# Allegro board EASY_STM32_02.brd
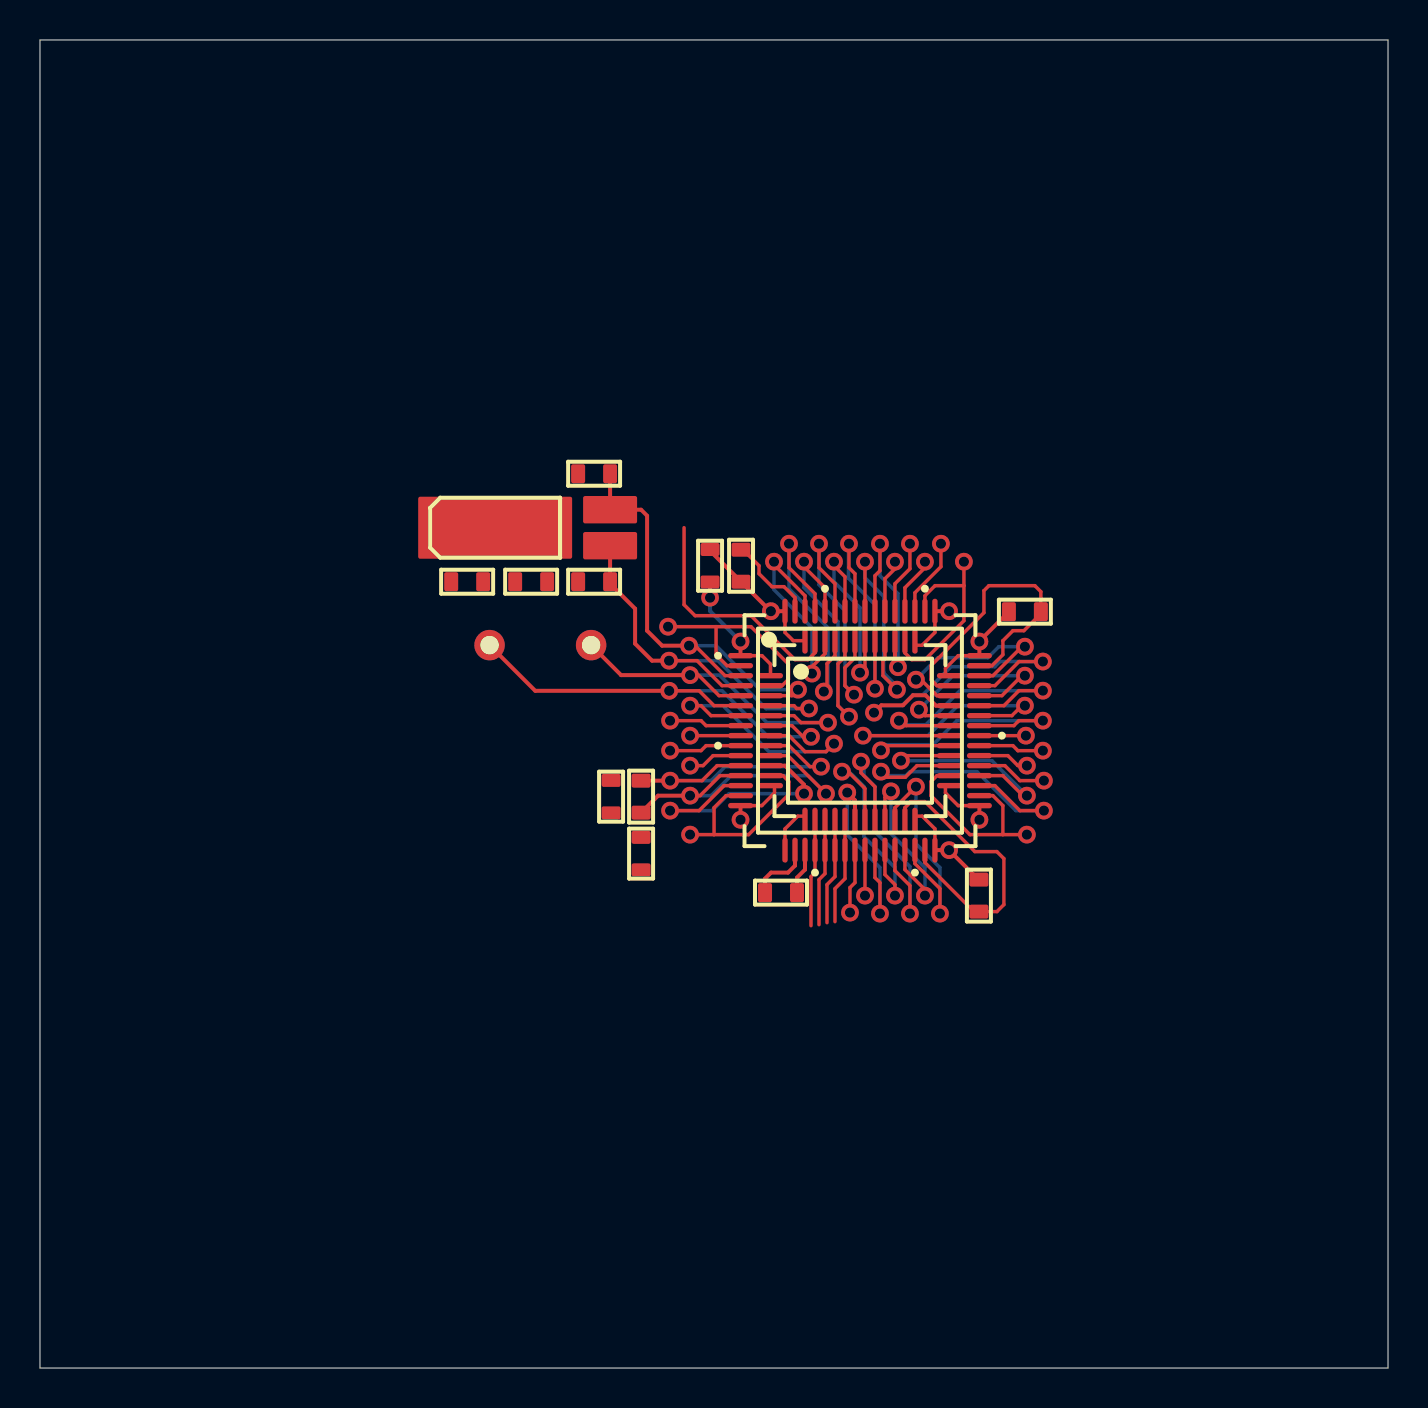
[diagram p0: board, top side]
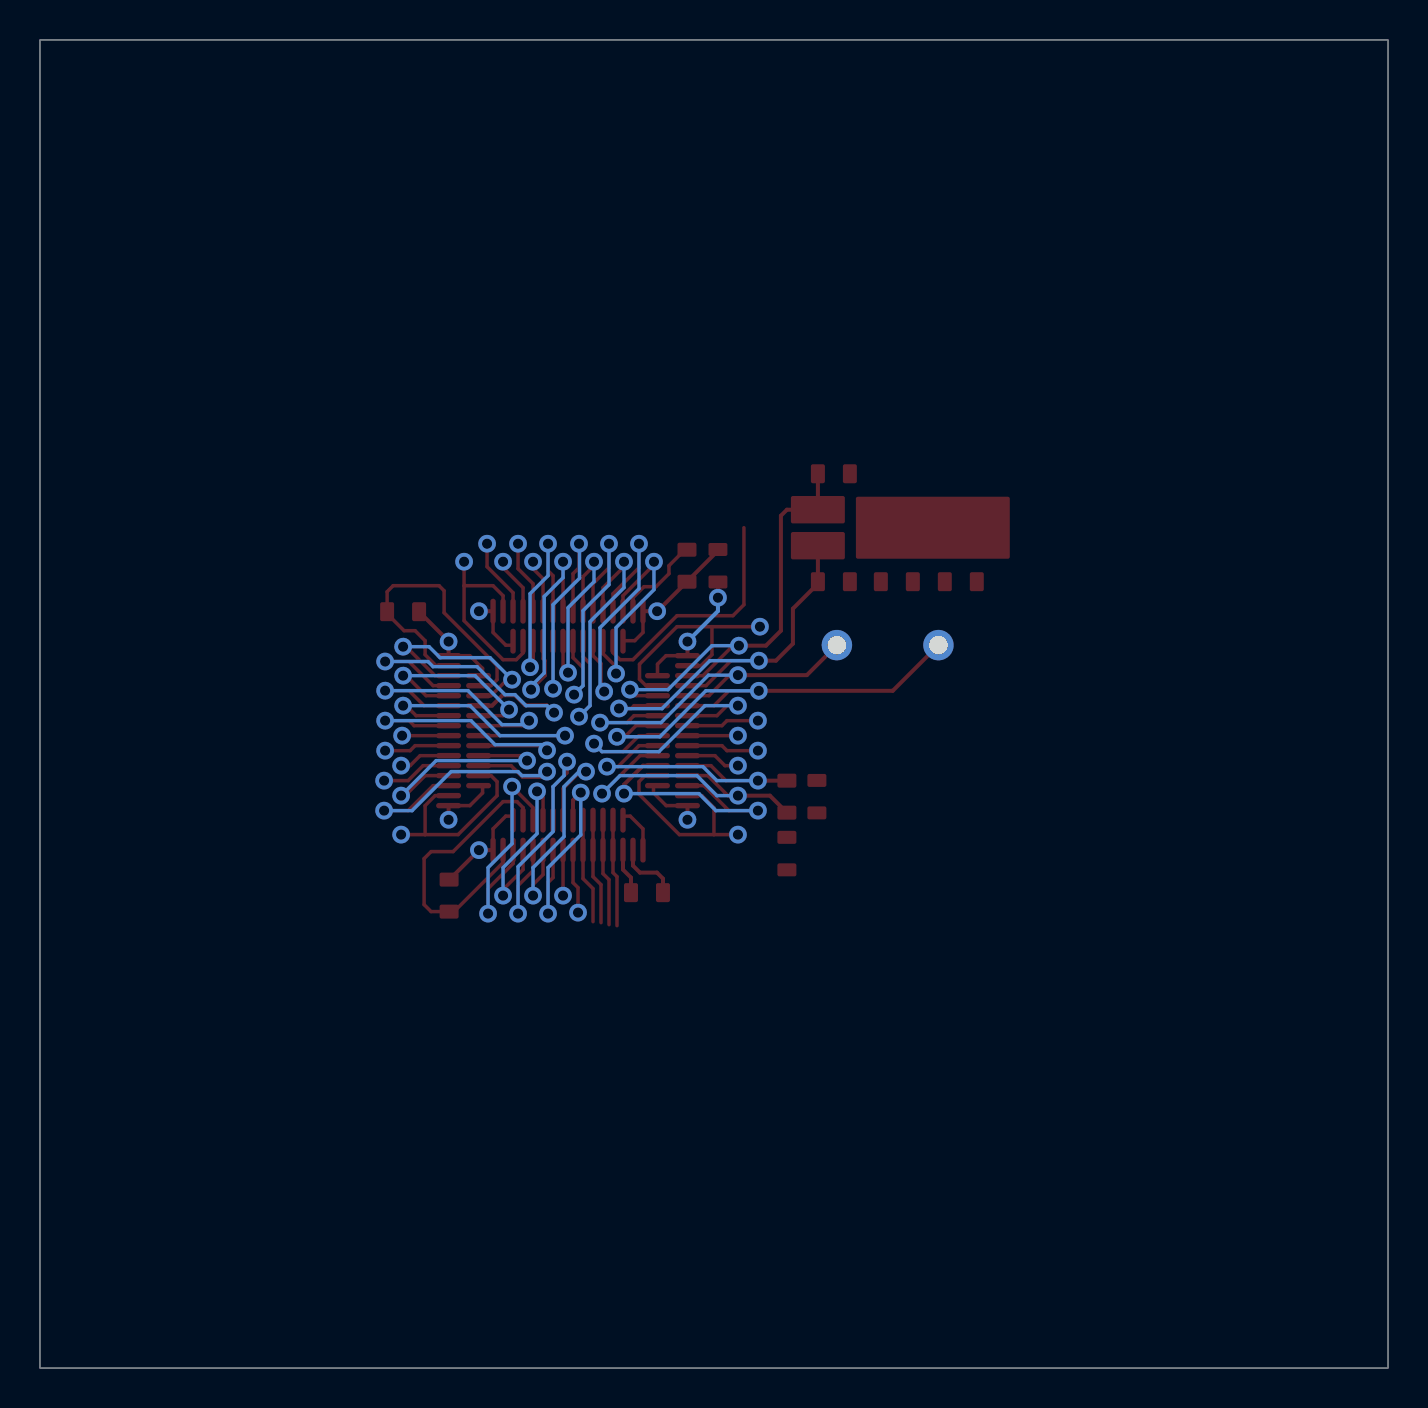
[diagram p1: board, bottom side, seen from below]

Outline 67.44 x 66.42 mm; copper layers: TOP, BOTTOM. Coordinates in mm from the lower left corner of the outline.
Outline path: 0,66.42 0,0 67.44,0 67.44,66.42 0,66.42

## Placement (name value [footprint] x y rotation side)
C1  22pF  [CAP0603_B]  24.57 39.33 180 top
C2  22p  [CAP0603_B]  21.37 39.33 0 top
C3  15p  [CAP0603_B]  27.72 39.33 180 top
C4  15p  [CAP0603_B]  27.72 44.73 180 top
C5  100n  [CAP0603_B]  30.07 28.58 90 top
C6  100n  [CAP0603_B]  46.97 23.63 270 top
C7  100n  [CAP0603_B]  49.27 37.83 0 top
C8  100n  [CAP0603_B]  35.07 40.13 90 top
C9  100n  [CAP0603_B]  37.07 23.78 180 top
R1  0R  [RES0603_B]  33.52 40.13 90 top
R2  0R  [RES0603_B]  30.07 25.73 270 top
R3  0R  [RES0603_B]  28.57 28.58 270 top
U1  STM32F103RCT6  [LQFP64_MODIFIED]  41.02 31.88 0 top
U2  STM32F100  [LQFP48L_MODIFIED]  41.02 31.88 0 top
Y1  8M  [CRYS11MHZ]  22.49 36.16 0 top
Y2  32.768KHz  [RTC-CRYSTAL]  24.52 42.03 90 top

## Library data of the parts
C1-C9 = C1005_0: User Part Number: pn; Tolerance: RichardLC
R1-R3 = R_0: User Part Number: pn; Tolerance: RichardLC
U1 = STM32F103RCT6_2: User Part Number: pn; Tolerance: RichardLC
U2 = STM32F100_1: User Part Number: pn; Tolerance: RichardLC
Y1 = ZTB: Tolerance: ***; User Part Number: ***
Y2 = ZTA_0: User Part Number: pn; Tolerance: RichardLC

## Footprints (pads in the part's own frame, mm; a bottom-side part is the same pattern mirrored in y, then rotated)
CAP0603_B
  custom 0.175x0.175 smd: 1(-0.8,0) 2(0.8,0)
CRYS11MHZ
  round 1.524 hole 0.914: 1(0,0) 2(5.08,0)
LQFP48L_MODIFIED
  oval 1.25x0.27 smd: 1(-4.475,2.75) 2(-4.475,2.25) 3(-4.475,1.75) 4(-4.475,1.25) 5(-4.475,0.75) 6(-4.475,0.25) 7(-4.475,-0.25) 8(-4.475,-0.75) 9(-4.475,-1.25) 10(-4.475,-1.75) 11(-4.475,-2.25) 12(-4.475,-2.75) 25(4.475,-2.75) 26(4.475,-2.25) 27(4.475,-1.75) 28(4.475,-1.25) 29(4.475,-0.75) 30(4.475,-0.25) 31(4.475,0.25) 32(4.475,0.75) 33(4.475,1.25) 34(4.475,1.75) 35(4.475,2.25) 36(4.475,2.75)
  oval 0.27x1.25 smd: 13(-2.75,-4.475) 14(-2.25,-4.475) 15(-1.75,-4.475) 16(-1.25,-4.475) 17(-0.75,-4.475) 18(-0.25,-4.475) 19(0.25,-4.475) 20(0.75,-4.475) 21(1.25,-4.475) 22(1.75,-4.475) 23(2.25,-4.475) 24(2.75,-4.475) 37(2.75,4.475) 38(2.25,4.475) 39(1.75,4.475) 40(1.25,4.475) 41(0.75,4.475) 42(0.25,4.475) 43(-0.25,4.475) 44(-0.75,4.475) 45(-1.25,4.475) 46(-1.75,4.475) 47(-2.25,4.475) 48(-2.75,4.475)
LQFP64_MODIFIED
  oval 1.25x0.27 smd: 1(-5.975,3.75) 2(-5.975,3.25) 3(-5.975,2.75) 4(-5.975,2.25) 5(-5.975,1.75) 6(-5.975,1.25) 7(-5.975,0.75) 8(-5.975,0.25) 9(-5.975,-0.25) 10(-5.975,-0.75) 11(-5.975,-1.25) 12(-5.975,-1.75) 13(-5.975,-2.25) 14(-5.975,-2.75) 15(-5.975,-3.25) 16(-5.975,-3.75) 33(5.975,-3.75) 34(5.975,-3.25) 35(5.975,-2.75) 36(5.975,-2.25) 37(5.975,-1.75) 38(5.975,-1.25) 39(5.975,-0.75) 40(5.975,-0.25) 41(5.975,0.25) 42(5.975,0.75) 43(5.975,1.25) 44(5.975,1.75) 45(5.975,2.25) 46(5.975,2.75) 47(5.975,3.25) 48(5.975,3.75)
  oval 0.27x1.25 smd: 17(-3.75,-5.975) 18(-3.25,-5.975) 19(-2.75,-5.975) 20(-2.25,-5.975) 21(-1.75,-5.975) 22(-1.25,-5.975) 23(-0.75,-5.975) 24(-0.25,-5.975) 25(0.25,-5.975) 26(0.75,-5.975) 27(1.25,-5.975) 28(1.75,-5.975) 29(2.25,-5.975) 30(2.75,-5.975) 31(3.25,-5.975) 32(3.75,-5.975) 49(3.75,5.975) 50(3.25,5.975) 51(2.75,5.975) 52(2.25,5.975) 53(1.75,5.975) 54(1.25,5.975) 55(0.75,5.975) 56(0.25,5.975) 57(-0.25,5.975) 58(-0.75,5.975) 59(-1.25,5.975) 60(-1.75,5.975) 61(-2.25,5.975) 62(-2.75,5.975) 63(-3.25,5.975) 64(-3.75,5.975)
RES0603_B
  custom 0.163x0.163 smd: 1(-0.812,0) 2(0.812,0)
RTC-CRYSTAL
  custom 0.343x0.343 smd: 1(-0.9,-4) 2(0.9,-4)
  custom 0.775x0.775 smd: 3(0,1.75)

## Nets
+3V3: C6.1 C7.1 C8.1 C9.1 R1.2 R2.2 U1.19(VDD_4) U1.32(VDD_1) U1.48(VDD_2) U1.64(VDD_3) U2.24(VDD_1) U2.36(VDD_2) U2.48(VDD_3)
GND: C1.2 C2.2 C3.2 C4.2 C6.2 C7.2 C8.2 C9.2 R3.2 U1.18(VSS_4) U1.31(VSS_1) U1.47(VSS_2) U1.63(VSS_3) U2.23(VSS_1) U2.35(VSS_2) U2.47(VSS_3) Y2.3
VBAT: R1.1 U1.1(VBAT) U2.1(VBAT)
VDDA: C5.1 R2.1 U1.13(VDDA) U2.9(VDDA)
VSSA: C5.2 R3.1 U1.12(VSSA) U2.8(VSSA)
BOOT0: U1.60(BOOT0) U2.44(BOOT0)
NRST: U1.7(NRST) U2.7(NRST)
OSC32_IN: C4.1 U1.3(PC14/OSC32_IN) U2.3(PC14/OSC32_IN) Y2.2
OSC32_OUT: C3.1 U1.4(PC15/OSC32/OUT) U2.4(PC15/OSC32_OUT) Y2.1
OSC_IN: C1.1 U1.5(PD0/OSC_IN) U2.5(PD0/OSC_IN) Y1.2
OSC_OUT: C2.1 U1.6(PD1/OSC_OUT) U2.6(PD1/OSC_OUT) Y1.1
PA0: U1.14(PA0-WKUP) U2.10(PA0/WKUP)
PA1: U1.15(PA1) U2.11(PA1)
PA2: U1.16(PA2) U2.12(PA2)
PA3: U1.17(PA3) U2.13(PA3)
PA4: U1.20(PA4) U2.14(PA4)
PA5: U1.21(PA5) U2.15(PA5)
PA6: U1.22(PA6) U2.16(PA6)
PA7: U1.23(PA7) U2.17(PA7)
PA8: U1.41(PA8) U2.29(PA8)
PA9: U1.42(PA9) U2.30(PA9)
PA10: U1.43(PA10) U2.31(PA10)
PA11: U1.44(PA11) U2.32(PA11)
PA12: U1.45(PA12) U2.33(PA12)
PA13: U1.46(PA13) U2.34(PA13)
PA14: U1.49(PA14) U2.37(PA14)
PA15: U1.50(PA15) U2.38(PA15)
PB0: U1.26(PB0) U2.18(PB0)
PB1: U1.27(PB1) U2.19(PB1)
PB2: U1.28(PB2/BOOT1) U2.20(PB2)
PB3: U1.55(PB3) U2.39(PB3)
PB4: U1.56(PB4) U2.40(PB4)
PB5: U1.57(PB5) U2.41(PB5)
PB6: U1.58(PB6) U2.42(PB6)
PB7: U1.59(PB7) U2.43(PB7)
PB8: U1.61(PB8) U2.45(PB8)
PB9: U1.62(PB9) U2.46(PB9)
PB10: U1.29(PB10) U2.21(PB10)
PB11: U1.30(PB11) U2.22(PB11)
PB12: U1.33(PB12) U2.25(PB12)
PB13: U1.34(PB13) U2.26(PB13)
PB14: U1.35(PB14) U2.27(PB14)
PB15: U1.36(PB15) U2.28(PB15)
PC0: U1.8(PC0)
PC1: U1.9(PC1)
PC2: U1.10(PC2)
PC3: U1.11(PC3)
PC4: U1.24(PC4)
PC5: U1.25(PC5)
PC6: U1.37(PC6)
PC7: U1.38(PC7)
PC8: U1.39(PC8)
PC9: U1.40(PC9)
PC10: U1.51(PC10)
PC11: U1.52(PC11)
PC12: U1.53(PC12)
PC13: U1.2(PC13/TAMPER/RTC) U2.2(PC13/TAMPER/RTC)
PD2: U1.54(PD2)

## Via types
v1: diameter 0.889, hole 0.508, TOP to BOTTOM, 84 vias

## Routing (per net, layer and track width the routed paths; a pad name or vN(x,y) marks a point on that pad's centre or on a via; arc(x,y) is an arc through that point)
+3V3: length 19.8
  TOP w0.175: U1.48 45.93,35.63 45.3,34.99 45.3,34.63 ; U1.64 37.27,36.79 37.68,36.38 38.27,36.38 ; U1.32 44.77,26.97 44.13,27.6 43.77,27.6
  TOP w0.2: U1.48 v1(47,36.33) 47,36.35 C7.1 ; U1.32 v1(45.48,25.9) 46.95,24.43 ; U1.64 v1(36.56,37.85) 36.55,37.85 C8.1 33.52,40.88 R1.2 ; U1.19 38.27,24.93 37.87,24.53 C9.1
GND: length 50.2
  TOP w0.175: U2.47 38.77,35.78 38.42,35.43 37.77,35.43 35.57,37.63 32.77,37.63 32.22,38.18 32.22,42.03 ; U1.47 47.62,35.13 48.17,35.68 48.17,36.38 48.67,36.88 49.22,36.88 50.07,37.73 C7.2 50.07,38.83 49.77,39.13 47.47,39.13 47.22,38.88 47.22,37.78 44.57,35.13 44.57,34.43 44.87,34.13 U2.35 ; U1.31 44.27,25.28 46.72,22.83 C6.2 47.87,22.83 48.22,23.18 48.22,25.48 47.87,25.83 46.77,25.83 44.27,28.33 43.57,28.33 43.27,28.03 43.27,27.6 ; C8.2 35.17,40.93 35.97,40.13 35.97,39.73 36.62,39.08 37.22,39.08 37.77,38.53 U1.63
  TOP w0.2: U1.18 37.77,25.13 37.42,24.78 36.57,24.78 36.27,24.48 C9.2
VBAT: length 6.6
  TOP w0.175: U2.1 36.55,35.2 36.12,35.63 U1.1
  TOP w0.2: U1.1 v1(35.05,36.33) ; R1.1 v1(33.52,38.53)
  BOTTOM w0.2: v1(35.05,36.33) 33.52,37.86 v1(33.52,38.53)
VDDA: length 16.9
  TOP w0.175: v1(32.52,28.63) 33.02,28.63 34.02,29.63 U1.13 ; v1(39.32,28.73) 37.42,30.63 U2.9
  TOP w0.2: C5.1 30.92,28.63 v1(32.52,28.63)
  BOTTOM w0.175: v1(39.32,28.73) 38.42,29.63 34.57,29.63 33.57,28.63 v1(32.52,28.63)
VSSA: length 16.1
  TOP w0.175: v1(39.07,30.08) 38.52,30.08 37.47,31.13 U2.8 ; U1.12 33.87,30.13 33.12,29.38 v1(31.52,29.38)
  TOP w0.2: v1(31.52,29.38) C5.2
  BOTTOM w0.175: v1(31.52,29.38) 33.57,29.38 34.27,30.08 v1(39.07,30.08)
BOOT0: length 15.7
  TOP w0.175: U1.60 39.27,39.03 38.22,40.08 v1(38.22,40.33) ; U2.44 40.27,35.58 39.92,35.23 39.92,33.13 v1(40.47,32.58)
  BOTTOM w0.175: v1(40.47,32.58) 39.92,33.13 39.92,37.33 38.22,39.03 v1(38.22,40.33)
NRST: length 14.7
  TOP w0.175: U2.7 37.47,31.63 38.27,30.83 39.32,30.83 v1(39.72,31.23) ; U1.7 33.57,32.63 33.07,33.13 v1(32.52,33.13)
  BOTTOM w0.175: v1(32.52,33.13) 34.17,33.13 36.47,30.83 39.32,30.83 v1(39.72,31.23)
OSC32_IN: length 23
  TOP w0.175: v1(32.47,36.13) 32.77,36.13 34.27,34.63 U1.3 ; U2.3 37.62,33.63 v1(37.92,33.93)
  TOP w0.2: v1(32.47,36.13) 31.12,36.13 30.37,36.88 30.37,42.63 30.07,42.93 Y2.2 C4.1
  BOTTOM w0.175: v1(37.92,33.93) 36.02,33.93 33.82,36.13 v1(32.47,36.13)
OSC32_OUT: length 21.5
  TOP w0.175: U1.4 34.12,34.13 32.87,35.38 v1(31.47,35.38) ; U2.4 37.72,33.13 37.86,32.98 v1(38.47,32.98)
  TOP w0.2: v1(31.47,35.38) 30.62,35.38 29.77,36.23 29.77,37.98 28.52,39.23 C3.1 Y2.1
  BOTTOM w0.175: v1(31.47,35.38) 33.92,35.38 36.32,32.98 38.46,32.98 v1(38.47,32.98)
OSC_IN: length 19.4
  TOP w0.175: v1(32.52,34.66) 32.94,34.66 33.97,33.63 U1.5 ; U2.5 37.72,32.63 38.07,32.28 v1(39.42,32.28)
  TOP w0.2: v1(32.52,34.66) 29.07,34.66 Y1.2
  BOTTOM w0.175: v1(39.42,32.28) 36.37,32.28 33.99,34.66 v1(32.52,34.66)
OSC_OUT: length 24.1
  TOP w0.175: U2.6 37.62,32.13 38.18,31.57 v1(38.57,31.57) ; v1(31.48,33.87) 32.98,33.87 33.72,33.13 U1.6
  TOP w0.2: Y1.1 24.78,33.87 v1(31.48,33.87)
  BOTTOM w0.175: v1(31.48,33.87) 34.13,33.87 36.43,31.57 v1(38.57,31.57)
PA0: length 13.6
  TOP w0.175: U1.14 34.22,29.13 32.97,27.88 v1(31.52,27.88)
  TOP w0.2: U2.10 37.27,30.13 38.22,29.18 v1(38.22,28.73)
  BOTTOM w0.175: v1(38.22,28.73) 34.47,28.73 33.62,27.88 v1(31.52,27.88)
PA1: length 10.2
  TOP w0.175: v1(32.52,26.68) 33.72,26.68 ; 33.72,26.68 33.72,28.03 34.32,28.63 U1.15 ; 33.72,26.68 35.45,26.68 37.47,28.7 37.47,29.33 37.17,29.63 36.75,29.63
PA2: length 3
  TOP w0.175: 36.75,29.13 36.75,28.76 36.11,28.13 U1.16
  TOP w0.2: U1.16 v1(35.05,27.42)
PA3: length 2.3
  TOP w0.175: U1.17 37.27,26.97 37.91,27.6 38.27,27.6
PA4: length 5.6
  TOP w0.175: 38.57,22.13 38.57,24.58 38.77,24.78 U1.20 U2.14 38.77,27.6
PA5: length 5.5
  TOP w0.175: 38.97,22.18 38.97,24.43 39.27,24.73 U1.21 U2.15 39.27,27.6
PA6: length 5.5
  TOP w0.175: 39.77,27.6 U2.16 U1.22 39.77,24.58 39.37,24.18 39.37,22.28
PA7: length 5.5
  TOP w0.175: 39.77,22.33 39.77,23.98 40.27,24.48 U1.23 U2.17 40.27,27.6
PA8: length 15.5
  TOP w0.175: U1.41 48.72,32.13 48.97,32.38 v1(50.17,32.38) ; U2.29 42.32,31.13 42.09,30.89 v1(42.07,30.89)
  BOTTOM w0.175: v1(42.07,30.89) 42.36,31.18 44.67,31.18 45.87,32.38 v1(50.17,32.38)
PA9: length 15.5
  TOP w0.175: U1.42 48.62,32.63 49.12,33.13 v1(49.27,33.13) ; v1(41.17,31.63) U2.30
  BOTTOM w0.175: v1(49.27,33.13) 45.92,33.13 44.42,31.63 v1(41.17,31.63)
PA10: length 14.1
  TOP w0.175: v1(42.97,32.38) 43.07,32.38 43.32,32.13 U2.31 ; U1.43 48.22,33.13 48.97,33.88 v1(50.17,33.88)
  BOTTOM w0.175: v1(50.17,33.88) 46.02,33.88 44.32,32.18 43.17,32.18 v1(42.97,32.38)
PA11: length 10.3
  TOP w0.175: U2.32 44.27,32.63 v1(43.97,32.93) ; U1.44 48.12,33.63 49.12,34.63 v1(49.27,34.63)
  BOTTOM w0.175: v1(49.27,34.63) 45.67,34.63 v1(43.97,32.93)
PA12: length 17.5
  TOP w0.175: v1(50.17,35.33) 48.98,35.33 47.77,34.13 U1.45
  TOP w0.2: U2.33 44.82,33.13 44.3,33.65 43.67,33.65 43.17,33.15 42.09,33.15 v1(41.72,32.78)
  BOTTOM w0.175: v1(41.72,32.78) 42.07,33.13 43.12,33.13 43.67,33.68 44.17,33.68 45.57,35.08 47.77,35.08 48.03,35.33 v1(50.17,35.33)
PA13: length 11
  TOP w0.175: U2.34 44.87,33.63 44.07,34.43 v1(43.82,34.43) ; U1.46 47.67,34.63 49.12,36.08 v1(49.27,36.08)
  BOTTOM w0.175: v1(49.27,36.08) 47.97,36.08 47.42,35.53 44.92,35.53 v1(43.82,34.43)
PA14: length 3
  TOP w0.175: 43.77,36.15 44.13,36.15 44.77,36.79 U1.49
  TOP w0.2: U1.49 v1(45.48,37.85)
PA15: length 10.4
  TOP w0.175: U1.50 44.27,38.63 44.77,39.13 46.22,39.13 ; 46.22,39.13 v1(46.22,40.33) ; 46.22,39.13 46.22,37.38 44.27,35.43 43.61,35.43 43.27,35.77 U2.38
PB0: length 11.5
  TOP w0.175: v1(42.02,22.73) 42.02,24.28 41.77,24.53 U1.26
  TOP w0.2: v1(40.38,28.78) 40.77,28.39 U2.18
  BOTTOM w0.175: v1(40.38,28.78) 40.38,26.66 42.02,25.03 v1(42.02,22.73)
PB1: length 13.1
  TOP w0.175: U1.27 42.27,24.68 42.77,24.18 v1(42.77,23.63) ; v1(40.12,29.83) 40.42,29.83 41.27,28.98 U2.19
  BOTTOM w0.175: v1(42.77,23.63) 42.77,25.03 41.22,26.58 41.22,29.08 40.47,29.83 v1(40.12,29.83)
PB2: length 15.3
  TOP w0.175: U1.28 42.77,24.88 43.52,24.13 v1(43.52,22.73) ; v1(41.07,30.33) 41.07,29.77 41.77,29.07 U2.20
  BOTTOM w0.175: v1(43.52,22.73) 43.52,25.08 41.77,26.83 41.77,29.08 41.22,29.63 41.22,30.18 v1(41.07,30.33)
PB3: length 11.4
  TOP w0.175: v1(42.02,41.23) 42.02,39.88 41.77,39.63 U1.55
  TOP w0.2: v1(42.92,35.05) 42.77,35.2 U2.39
  BOTTOM w0.175: v1(42.02,41.23) 42.02,39.63 42.92,38.73 v1(42.92,35.05)
PB4: length 12.3
  TOP w0.175: v1(42.87,33.93) 42.17,34.63 42.17,35.38 42.27,35.48 U2.40 ; U1.56 v1(41.27,40.33)
  BOTTOM w0.175: v1(41.27,40.33) 41.27,39.53 42.21,38.58 42.21,34.76 42.87,34.1 v1(42.87,33.93)
PB5: length 13.7
  TOP w0.175: U1.57 40.77,39.73 40.47,40.03 v1(40.47,41.23) ; U2.41 v1(41.77,33.98)
  BOTTOM w0.175: v1(41.77,33.98) 41.77,38.18 40.45,39.5 40.45,41.2 v1(40.47,41.23)
PB6: length 10.5
  TOP w0.175: U2.42 41.27,35.03 v1(41.02,34.78) ; v1(39.72,40.33) 39.72,40.13 40.27,39.58 U1.58
  BOTTOM w0.175: v1(41.02,34.78) 41.02,38.03 39.72,39.33 v1(39.72,40.33)
PB7: length 15
  TOP w0.175: v1(40.72,33.68) 40.27,34.13 40.27,35.03 40.77,35.53 U2.43 ; U1.59 39.77,39.23 38.97,40.03 v1(38.97,41.23)
  BOTTOM w0.175: v1(40.72,33.68) 40.27,34.13 40.27,37.88 38.97,39.18 v1(38.97,41.23)
PB8: length 15
  TOP w0.175: v1(37.47,41.23) 37.47,40.03 38.77,38.73 U1.61 ; U2.45 39.77,35.63 39.37,35.23 39.37,33.99 v1(39.21,33.83)
  BOTTOM w0.175: v1(39.21,33.83) 39.42,34.04 39.42,37.03 37.47,38.98 v1(37.47,41.23)
PB9: length 11.4
  TOP w0.175: U2.46 39.27,35.73 38.62,35.07 v1(38.62,34.73) ; U1.62 38.27,38.63 36.72,40.18 v1(36.72,40.33)
  BOTTOM w0.175: v1(36.72,40.33) 36.72,38.93 38.62,37.03 v1(38.62,34.73)
PB10: length 10.2
  TOP w0.175: U2.21 42.27,28.54 v1(42.57,28.84) ; v1(44.27,23.63) 44.27,23.93 43.27,24.93 U1.29
  BOTTOM w0.175: v1(42.57,28.84) 42.57,26.73 44.27,25.03 v1(44.27,23.63)
PB11: length 12.6
  TOP w0.175: U2.22 42.77,28.03 v1(43.82,29.08) ; U1.30 43.77,25.23 45.02,23.98 v1(45.02,22.73)
  BOTTOM w0.175: v1(45.02,22.73) 45.02,25.03 43.82,26.23 v1(43.82,29.08)
PB12: length 3
  TOP w0.175: 45.3,29.13 45.3,28.76 45.93,28.13 U1.33
  TOP w0.2: U1.33 v1(47,27.42)
PB13: length 10
  TOP w0.175: v1(49.37,26.68) 48.17,26.68 ; 48.17,26.68 46.52,26.68 44.57,28.63 44.57,29.33 44.87,29.63 45.3,29.63 ; 48.17,26.68 48.17,28.13 47.67,28.63 U1.34
PB14: length 16.6
  TOP w0.175: v1(50.22,27.88) 49.02,27.88 47.77,29.13 U1.35 ; U2.27 43.87,30.13 43.29,29.55 42.35,29.55 v1(42.07,29.83)
  BOTTOM w0.175: v1(42.07,29.83) 42.27,29.63 43.32,29.63 43.52,29.83 46.87,29.83 48.82,27.88 v1(50.22,27.88)
PB15: length 12.3
  TOP w0.175: U2.28 43.32,30.63 v1(43.07,30.38) ; U1.36 48.17,29.63 49.17,28.63 v1(49.37,28.63)
  BOTTOM w0.175: v1(49.37,28.63) 47.62,30.38 v1(43.07,30.38)
PC0: length 3.6
  TOP w0.175: U1.8 33.32,32.13 33.07,32.38 v1(31.52,32.38)
PC1: length 2.5
  TOP w0.175: U1.9 v1(32.52,31.63)
PC2: length 3.6
  TOP w0.175: U1.10 33.32,31.13 33.07,30.88 v1(31.52,30.88)
PC3: length 2.7
  TOP w0.175: v1(32.52,30.13) 33.17,30.13 33.67,30.63 U1.11
PC4: length 3.2
  TOP w0.175: v1(40.52,22.78) 40.52,24.03 40.77,24.28 U1.24
PC5: length 2.3
  TOP w0.175: U1.25 v1(41.27,23.63)
PC6: length 3.5
  TOP w0.175: v1(50.22,29.38) 49.02,29.38 48.27,30.13 U1.37
PC7: length 2.6
  TOP w0.175: U1.38 48.42,30.63 48.92,30.13 v1(49.37,30.13)
PC8: length 3.3
  TOP w0.175: U1.39 48.67,31.13 48.92,30.88 v1(50.17,30.88)
PC9: length 2.3
  TOP w0.175: U1.40 v1(49.32,31.63)
PC10: length 3.9
  TOP w0.175: v1(45.07,41.23) 45.07,40.08 43.77,38.78 U1.51
PC11: length 2.9
  TOP w0.175: U1.52 43.27,39.03 44.27,40.03 v1(44.27,40.33)
PC12: length 3.7
  TOP w0.175: v1(43.52,41.23) 43.52,39.98 42.77,39.23 U1.53
PC13: length 11.4
  TOP w0.175: U2.2 37.12,34.13 37.45,34.45 37.45,35.2 35.57,37.08 33.82,37.08 ; 33.82,37.08 v1(31.42,37.08) ; 33.82,37.08 33.82,35.68 34.37,35.13 U1.2
PD2: length 2.7
  TOP w0.175: U1.54 42.27,39.48 42.77,39.98 v1(42.77,40.33)

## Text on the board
COMPVAL_TYPE_TOP: FIGURE | SIZE | 0.508 | 0.8 | 0.8999 | 0.9144 | 1.0 | 2.4 | DRILL CHART: TOP to BOTTOM | ALL UNITS ARE IN MILLIMETERS | PLATED | QTY | 121 | 14 | 200 | 2 | 4
